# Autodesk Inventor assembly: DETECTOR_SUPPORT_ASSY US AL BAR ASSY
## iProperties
Shininess: 64.0
Length Units: 11272
Angle Units: 11279
Time Units: 11290
Mass Units: 11286
Length Display Precision: 3
Angle Display Precision: 2
Compacted: True
Part Number: DETECTOR_SUPPORT_ASSY US AL BAR ASSY
Document SubType Name: Assembly
Created: 2004-08
Designer: John Blackburn
Manufacturer: Standard
Standards Organization: Custom
Density: 0.0
Volumn: 0.0
Area: 0.0
PropertySet Name: Model Information
Control State: 0
Master: False
Checked Out: False
Author: John Blackburn
